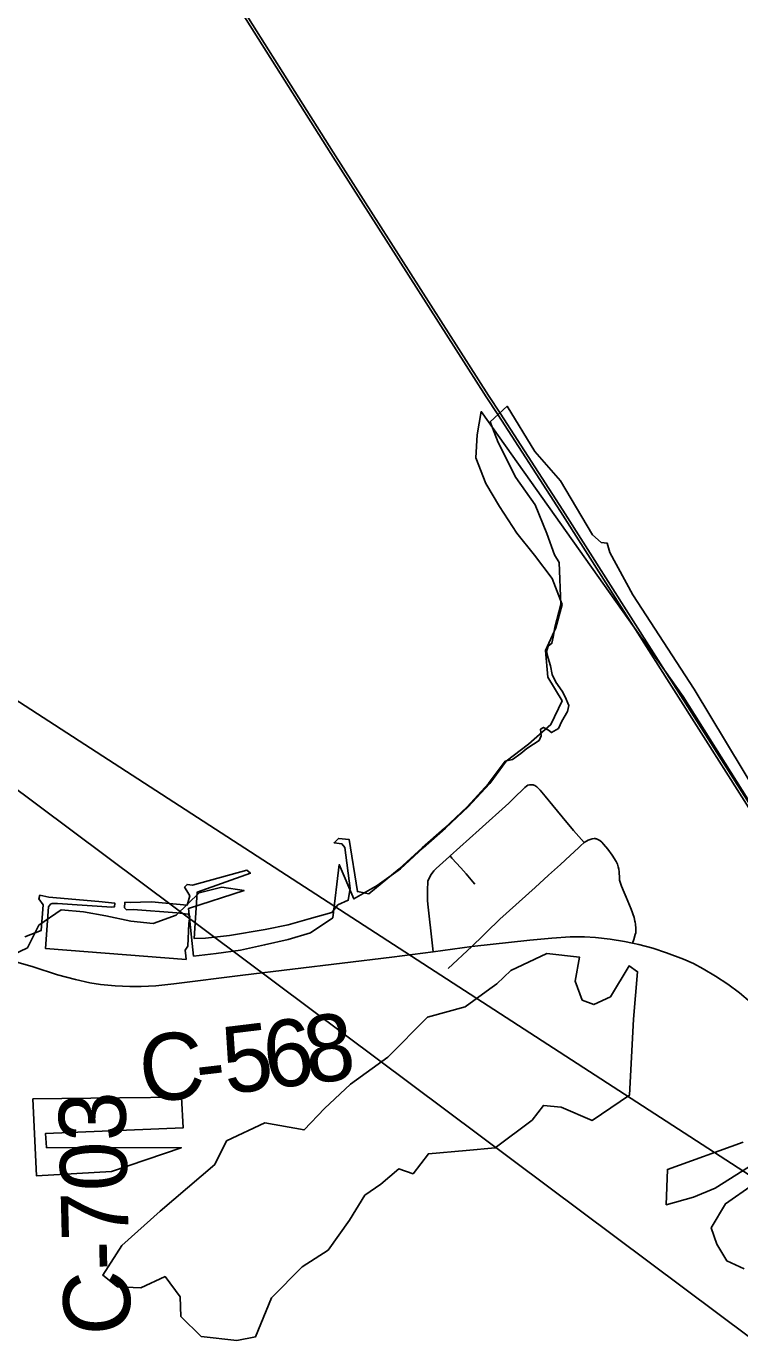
# Model space of a CAD drawing. Extents: x 0 to 34, y 0 to 22.
# Drawn here: x 6.753 to 7.056, y 16.659 to 17.217 of the extents above; entities that cross this region are included whole.
import ezdxf

# ---------------------------------------------------------------- set-up
doc = ezdxf.new("R2010")
doc.units = 0
for name, color, linetype in [('GM_X_Corporation', 7, 'Continuous'), ('GM_X_County_Road', 7, 'Continuous'), ('GM_X_County_Road_Text', 7, 'Continuous'), ('GM_X_Major_Lake', 7, 'Continuous'), ('GM_X_Minor_River', 7, 'Continuous'), ('GM_X_Rail_Line', 7, 'Continuous'), ('GM_X_Township_Road', 7, 'Continuous'), ('SH_Text', 7, 'Continuous')]:
    doc.layers.add(name, color=color, linetype=linetype)

msp = doc.modelspace()

# ---------------------------------------------------------------- linework, layer by layer
at = {"layer": 'GM_X_Corporation'}
msp.add_lwpolyline([(7.06359, 16.88957), (7.03618, 16.93515), (7.01014, 16.97532), (7.00034, 16.99321), (6.99924, 16.99721), (6.99668, 16.99755), (6.99302, 17.00078), (6.9794, 17.02378), (6.96858, 17.03621), (6.95675, 17.05545), (6.94951, 17.04882), (6.953, 17.03999), (6.96051, 17.02519), (6.96868, 17.01349), (6.97354, 17.00134), (6.97685, 16.99229), (6.97884, 16.98897), (6.97961, 16.97122), (6.97696, 16.96134), (6.97624, 16.95735), (6.97573, 16.95471), (6.9742, 16.95343), (6.97343, 16.95105), (6.9742, 16.94841), (6.97522, 16.94517), (6.97582, 16.94143), (6.97743, 16.93811), (6.98008, 16.93427), (6.98144, 16.93197), (6.98288, 16.92823), (6.98237, 16.92567), (6.97999, 16.92158), (6.97854, 16.91843), (6.97556, 16.91673), (6.97437, 16.91775), (6.97224, 16.91895), (6.97096, 16.91818), (6.97122, 16.91528), (6.97037, 16.91341), (6.9679, 16.91179), (6.96517, 16.91), (6.96253, 16.90779), (6.95896, 16.90523), (6.9559, 16.90457), (6.94888, 16.89507), (6.93977, 16.8852), (6.9301, 16.87608), (6.92061, 16.86772), (6.91094, 16.8588), (6.89795, 16.84824), (6.89312, 16.84918), (6.88962, 16.87133), (6.88506, 16.87173), (6.88325, 16.86989), (6.88657, 16.86938), (6.88785, 16.86793), (6.89014, 16.85047), (6.88928, 16.84549), (6.88487, 16.84358), (6.8823, 16.84033), (6.8727, 16.83757), (6.86369, 16.83509), (6.85394, 16.83306), (6.83879, 16.83055), (6.82866, 16.82936), (6.8238, 16.82927), (6.82516, 16.84891), (6.84769, 16.85691), (6.84624, 16.85822), (6.82308, 16.85187), (6.82082, 16.85218), (6.81972, 16.85107), (6.82065, 16.84954), (6.82201, 16.84741), (6.82079, 16.84338), (6.80567, 16.84484), (6.80108, 16.84469), (6.79666, 16.84455), (6.79444, 16.84461), (6.79426, 16.8423), (6.79502, 16.84145), (6.79791, 16.84153), (6.81648, 16.84017), (6.82125, 16.83949), (6.82201, 16.83855), (6.82159, 16.83557), (6.82116, 16.82595), (6.82006, 16.82425), (6.82023, 16.82178), (6.8204, 16.82033), (6.7607, 16.82493), (6.76198, 16.84264), (6.76275, 16.84375), (6.76351, 16.84409), (6.76581, 16.84409), (6.78889, 16.84255), (6.79, 16.84273), (6.79017, 16.84417), (6.7833, 16.84492), (6.76216, 16.8468), (6.7583, 16.84759), (6.7579, 16.84611), (6.75969, 16.84354), (6.75877, 16.83258), (6.75184, 16.82987)], dxfattribs=at)
msp.add_lwpolyline([(7.06359, 16.88957), (7.03618, 16.93515), (7.01014, 16.97532), (7.00034, 16.99321), (6.99924, 16.99721), (6.99668, 16.99755), (6.99302, 17.00078), (6.9794, 17.02378), (6.96858, 17.03621), (6.95675, 17.05545), (6.94951, 17.04882), (6.953, 17.03999), (6.96051, 17.02519), (6.96868, 17.01349), (6.97354, 17.00134), (6.97685, 16.99229), (6.97884, 16.98897), (6.97961, 16.97122), (6.97696, 16.96134), (6.97624, 16.95735), (6.97573, 16.95471), (6.9742, 16.95343), (6.97343, 16.95105), (6.9742, 16.94841), (6.97522, 16.94517), (6.97582, 16.94143), (6.97743, 16.93811), (6.98008, 16.93427), (6.98144, 16.93197), (6.98288, 16.92823), (6.98237, 16.92567), (6.97999, 16.92158), (6.97854, 16.91843), (6.97556, 16.91673), (6.97437, 16.91775), (6.97224, 16.91895), (6.97096, 16.91818), (6.97122, 16.91528), (6.97037, 16.91341), (6.9679, 16.91179), (6.96517, 16.91), (6.96253, 16.90779), (6.95896, 16.90523), (6.9559, 16.90457), (6.94888, 16.89507), (6.93977, 16.8852), (6.9301, 16.87608), (6.92061, 16.86772), (6.91094, 16.8588), (6.89795, 16.84824), (6.89312, 16.84918), (6.88962, 16.87133), (6.88506, 16.87173), (6.88325, 16.86989), (6.88657, 16.86938), (6.88785, 16.86793), (6.89014, 16.85047), (6.88928, 16.84549), (6.88487, 16.84358), (6.8823, 16.84033), (6.8727, 16.83757), (6.86369, 16.83509), (6.85394, 16.83306), (6.83879, 16.83055), (6.82866, 16.82936), (6.8238, 16.82927), (6.82516, 16.84891), (6.84769, 16.85691), (6.84624, 16.85822), (6.82308, 16.85187), (6.82082, 16.85218), (6.81972, 16.85107), (6.82065, 16.84954), (6.82201, 16.84741), (6.82079, 16.84338), (6.80567, 16.84484), (6.80108, 16.84469), (6.79666, 16.84455), (6.79444, 16.84461), (6.79426, 16.8423), (6.79502, 16.84145), (6.79791, 16.84153), (6.81648, 16.84017), (6.82125, 16.83949), (6.82201, 16.83855), (6.82159, 16.83557), (6.82116, 16.82595), (6.82006, 16.82425), (6.82023, 16.82178), (6.8204, 16.82033), (6.7607, 16.82493), (6.76198, 16.84264), (6.76275, 16.84375), (6.76351, 16.84409), (6.76581, 16.84409), (6.78889, 16.84255), (6.79, 16.84273), (6.79017, 16.84417), (6.7833, 16.84492), (6.76216, 16.8468), (6.7583, 16.84759), (6.7579, 16.84611), (6.75969, 16.84354), (6.75877, 16.83258), (6.75184, 16.82987)], dxfattribs=at)
at = {"layer": 'GM_X_County_Road'}
msp.add_line((6.92533, 16.82351), (6.94178, 16.82588), dxfattribs=at)
for points in [[(6.94178, 16.82588), (6.96644, 16.82852), (6.97571, 16.8294), (6.98345, 16.82985), (6.98964, 16.82988), (6.99428, 16.82963), (7.00045, 16.82898), (7.00658, 16.82799), (7.01003, 16.82724)], [(7.01003, 16.82724), (7.01265, 16.82667), (7.01864, 16.82507), (7.0245, 16.82311), (7.03162, 16.82038), (7.03583, 16.81852), (7.03995, 16.81638), (7.04528, 16.81324), (7.05042, 16.80979), (7.05537, 16.80606), (7.06015, 16.80211)], [(6.74312, 16.82072), (6.75545, 16.8171), (6.76583, 16.8138), (6.77335, 16.81176), (6.77945, 16.81041), (6.78408, 16.80968), (6.7903, 16.80903), (6.79655, 16.80875), (6.80124, 16.80879), (6.80748, 16.80914), (6.81523, 16.80989), (6.84454, 16.81358), (6.90781, 16.82132), (6.92533, 16.82351)]]:
    msp.add_lwpolyline(points, dxfattribs=at)
at = {"layer": 'GM_X_Major_Lake'}
for points in [[(6.94402, 17.04333), (6.94573, 17.0532), (7.03151, 16.93207), (7.06548, 16.87815), (7.09509, 16.83088), (7.1283, 16.77335), (7.14955, 16.74164), (7.18372, 16.69911), (7.19984, 16.69988), (7.20269, 16.71032)], [(6.74348, 16.82075), (6.75296, 16.82531), (6.75789, 16.83481), (6.76738, 16.84146), (6.77687, 16.84051), (6.78636, 16.8388), (6.79698, 16.83652), (6.80647, 16.83558), (6.81615, 16.83919), (6.82601, 16.84868), (6.8355, 16.85096), (6.84499, 16.84963), (6.82146, 16.84203), (6.82355, 16.82172), (6.83323, 16.82286), (6.84347, 16.82419), (6.85372, 16.82647), (6.86378, 16.82875), (6.87327, 16.8316), (6.88275, 16.83806), (6.88541, 16.86065), (6.89167, 16.84603), (6.90154, 16.85173), (6.9114, 16.85876), (6.92108, 16.86769), (6.93057, 16.87604), (6.94024, 16.88516), (6.94935, 16.89503), (6.95637, 16.90453), (6.96586, 16.91175), (6.97534, 16.9201), (6.98008, 16.93017), (6.97401, 16.94023), (6.97306, 16.95162), (6.97742, 16.96131), (6.98008, 16.97118), (6.9759, 16.98219), (6.96831, 16.99207), (6.96091, 17.00156), (6.95351, 17.01276), (6.94763, 17.02263), (6.94345, 17.03345), (6.94402, 17.04333)]]:
    msp.add_lwpolyline(points, dxfattribs=at)
at = {"layer": 'GM_X_Minor_River'}
for points in [[(6.94939, 16.80781), (6.93898, 16.8002), (6.92297, 16.79575), (6.90611, 16.77877), (6.89023, 16.76729), (6.87912, 16.75691), (6.8705, 16.74785), (6.85378, 16.75082), (6.83756, 16.74315), (6.83254, 16.73311), (6.80937, 16.71332), (6.7931, 16.69879), (6.78501, 16.68611), (6.79125, 16.68112), (6.80114, 16.68067), (6.81145, 16.68553), (6.81785, 16.67693), (6.81817, 16.66856), (6.82686, 16.66012), (6.84187, 16.6583), (6.84987, 16.65995), (6.85665, 16.67644), (6.86968, 16.68966), (6.88077, 16.6968), (6.8898, 16.70947), (6.89635, 16.72007), (6.90304, 16.72478), (6.9107, 16.73138), (6.91677, 16.72924), (6.9233, 16.73775), (6.93928, 16.73915), (6.95166, 16.74019), (6.96734, 16.75206), (6.97214, 16.7583), (6.97974, 16.75748), (6.99283, 16.75186), (7.00869, 16.76258), (7.01046, 16.7949), (7.01213, 16.81505), (7.00853, 16.81755), (7.00064, 16.80448), (6.99357, 16.80112), (6.98864, 16.80305), (6.98566, 16.81106), (6.98745, 16.82132), (6.97355, 16.8228)], [(6.97355, 16.8228), (6.9583, 16.81565), (6.95237, 16.80999), (6.94939, 16.80781)], [(6.75533, 16.76108), (6.7568, 16.72836), (6.78877, 16.73021), (6.81832, 16.74025), (6.76107, 16.74031), (6.76074, 16.7464), (6.81915, 16.74881), (6.81848, 16.76174), (6.7922, 16.76147)], [(6.7922, 16.76147), (6.75533, 16.76108)], [(7.05705, 16.74263), (7.02482, 16.73108), (7.02432, 16.71606), (7.03595, 16.71921), (7.04511, 16.72313), (7.05963, 16.73234)], [(7.06129, 16.72472), (7.04943, 16.71644), (7.04346, 16.70622), (7.04588, 16.69935), (7.05001, 16.69228), (7.05741, 16.6888)]]:
    msp.add_lwpolyline(points, dxfattribs=at)
at = {"layer": 'GM_X_Rail_Line'}
for points in [[(6.81333, 17.27153), (6.88193, 17.16285), (6.94789, 17.05939), (6.95276, 17.05186)], [(6.81432, 17.27215), (6.88292, 17.16347), (6.94887, 17.06002), (6.95374, 17.05249)], [(6.95276, 17.05186), (6.97939, 17.01066), (7.11617, 16.79529)], [(6.95374, 17.05249), (6.98037, 17.01129), (7.11716, 16.79592)]]:
    msp.add_lwpolyline(points, dxfattribs=at)
at = {"layer": 'GM_X_Township_Road'}
msp.add_line((6.93164, 16.8165), (6.94178, 16.82588), dxfattribs=at)
for points in [[(6.93249, 16.86433), (6.94489, 16.87541), (6.95749, 16.88675), (6.96074, 16.89), (6.96296, 16.89214), (6.96421, 16.89344), (6.96493, 16.89399), (6.96556, 16.89435), (6.96626, 16.89454), (6.96693, 16.89457)], [(6.98945, 16.86998), (6.98492, 16.87518), (6.98008, 16.88098), (6.97616, 16.88572), (6.97287, 16.88976), (6.97073, 16.8923), (6.96938, 16.89364), (6.96895, 16.89398), (6.9685, 16.89425), (6.96814, 16.89438), (6.96777, 16.89452), (6.96733, 16.89457), (6.96693, 16.89457)], [(6.98945, 16.86998), (6.99117, 16.87105), (6.99289, 16.87162)], [(7.01003, 16.82724), (7.01052, 16.8288), (7.01118, 16.83087), (7.01138, 16.83162), (7.01145, 16.83224), (7.01146, 16.83287), (7.0114, 16.83408), (7.01133, 16.83467), (7.01124, 16.83535), (7.01111, 16.83609), (7.01102, 16.83664), (7.01065, 16.83809), (7.00947, 16.84164), (7.00727, 16.84681), (7.00647, 16.84882), (7.00539, 16.85144), (7.00474, 16.85316), (7.0046, 16.85359), (7.00452, 16.85407), (7.00444, 16.85491), (7.00428, 16.85754), (7.00415, 16.8587), (7.00396, 16.85969), (7.0038, 16.86027), (7.00358, 16.86082), (7.00331, 16.86141), (7.00299, 16.86196), (7.00135, 16.86468), (6.99952, 16.8672), (6.9977, 16.86933), (6.99692, 16.87009), (6.99609, 16.87082), (6.99556, 16.87117), (6.99503, 16.87143), (6.99473, 16.87152), (6.99442, 16.87161), (6.99409, 16.87167), (6.99373, 16.8717), (6.99289, 16.87162)], [(6.94178, 16.82588), (6.94654, 16.83042), (6.94797, 16.83196), (6.95362, 16.83738), (6.96861, 16.85095), (6.97434, 16.85616), (6.97557, 16.8572), (6.97947, 16.86065), (6.98353, 16.86443), (6.98704, 16.86774), (6.98793, 16.8686), (6.98945, 16.86998)], [(6.92307, 16.85355), (6.92373, 16.85512), (6.92453, 16.85647), (6.92564, 16.85797), (6.92667, 16.859), (6.93221, 16.86408), (6.93249, 16.86433)], [(6.94299, 16.85235), (6.94212, 16.85336), (6.93933, 16.85667), (6.93702, 16.85919), (6.93329, 16.86342), (6.93249, 16.86433)], [(6.92533, 16.82351), (6.92491, 16.82743), (6.92327, 16.84252), (6.92299, 16.8452), (6.92294, 16.84964), (6.92307, 16.85355)]]:
    msp.add_lwpolyline(points, dxfattribs=at)
at = {"layer": 'SH_Text'}
msp.add_lwpolyline([(6.36862, 17.17654), (9.3797, 15.22429), (9.3797, 14.92419)], close=True, dxfattribs=at)

# ---------------------------------------------------------------- texts
at = {"layer": 'GM_X_County_Road_Text'}
for s, height, rotation, p in [('5', 0.02841, 6.9529, (6.8375, 16.76303)), ('6', 0.02841, 7.1243, (6.85496, 16.76517)), ('8', 0.02841, 7.1726, (6.87235, 16.76734)), ('C', 0.02841, 5.3234, (6.8018, 16.75943)), ('-', 0.02841, 6.6378, (6.82574, 16.76167)), ('C-703', 0.028409, 91.3635, (6.79697, 16.66095))]:
    msp.add_text(s, height=height, rotation=rotation, dxfattribs=at).set_placement(p)

doc.saveas('drawing.dxf')
